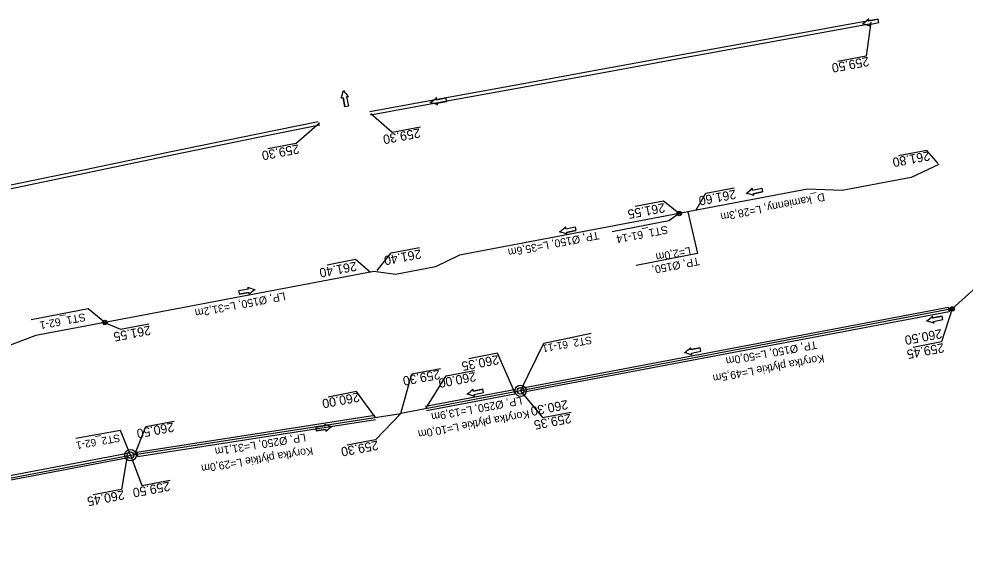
# Model space of a CAD drawing. Extents: x -1 to 65640748, y -22 to 5530284.
# Drawn here: x 6557044.8 to 6557152.5, y 5528580.5 to 5528641.5 of the extents above; entities that cross this region are included whole.
import ezdxf

# ---------------------------------------------------------------- set-up
doc = ezdxf.new("R2010")
doc.units = 0
for name, color, linetype in [('TOR_PROF-studnie i osadniki', 7, 'Continuous'), ('TOR_PS_ODW-drenaze', 7, 'Continuous'), ('TOR_PS_ODW-drenokolektory', 7, 'Continuous'), ('TOR_PS_ODW-studnie PEHD', 7, 'Continuous'), ('TOR_PS_OPIS_O-opisy rurociagow', 7, 'Continuous'), ('TOR_PS_OPIS_O-opisy studni', 7, 'Continuous'), ('TOR_PS_OPIS_T-INFO', 7, 'Continuous'), ('TOR_PS_T-rowy otwarte umocnione', 7, 'Continuous')]:
    doc.layers.add(name, color=color, linetype=linetype)

msp = doc.modelspace()

# ---------------------------------------------------------------- linework, layer by layer
at = {"layer": 'TOR_PROF-studnie i osadniki'}
for centre, radius in [((6557119.99, 5528619.34), 0.25), ((6557119.99, 5528619.34), 0.125), ((6557151.06, 5528608.48), 0.25), ((6557151.06, 5528608.48), 0.25), ((6557151.06, 5528608.48), 0.125), ((6557151.06, 5528608.48), 0.125), ((6557054.6, 5528606.95), 0.25), ((6557054.6, 5528606.95), 0.125), ((6557101.93, 5528599.17), 0.65), ((6557101.93, 5528599.17), 0.375), ((6557057.52, 5528591.83), 0.65), ((6557057.52, 5528591.83), 0.375)]:
    msp.add_circle(centre, radius, dxfattribs=at)
at = {"layer": 'TOR_PS_ODW-drenaze'}
for points in [[(6557149.52, 5528624.94), (6557146.39, 5528623.43), (6557138.55, 5528621.95), (6557134.58, 5528622.11), (6557121.96, 5528619.72)], [(6557121.96, 5528619.72), (6557119.99, 5528619.34)], [(6557119.99, 5528619.34), (6557094.96, 5528614.6), (6557092.25, 5528613.29), (6557087.68, 5528612.42), (6557085.22, 5528612.75)], [(6557151.06, 5528608.48), (6557101.93, 5528599.17)], [(6557054.6, 5528606.95), (6557046.73, 5528605.45), (6557043.51, 5528604.23), (6557029.81, 5528601.64), (6557026.15, 5528601.56)], [(6556998.57, 5528580.65), (6557057.52, 5528591.83)]]:
    msp.add_lwpolyline(points, dxfattribs=at)
at = {"layer": 'TOR_PS_ODW-drenokolektory'}
for points in [[(6557085.22, 5528612.75), (6557054.6, 5528606.95)], [(6557101.93, 5528599.17), (6557088.28, 5528596.59)], [(6557057.52, 5528591.83), (6557088.28, 5528596.59)]]:
    msp.add_lwpolyline(points, dxfattribs=at)
at = {"layer": 'TOR_PS_ODW-studnie PEHD'}
for centre, radius in [((6557119.99, 5528619.34), 0.25), ((6557119.99, 5528619.34), 0.112), ((6557054.6, 5528606.95), 0.25), ((6557054.6, 5528606.95), 0.112)]:
    msp.add_circle(centre, radius, dxfattribs=at)
at = {"layer": 'TOR_PS_OPIS_O-opisy rurociagow'}
for p, q in [((6557142.63, 5528641.46), (6557141.56, 5528641.27)), ((6557141.56, 5528641.27), (6557142.63, 5528641.46)), ((6557142.7, 5528641.07), (6557142.63, 5528641.46)), ((6557142.7, 5528641.07), (6557142.63, 5528641.46)), ((6557141.63, 5528640.87), (6557142.7, 5528641.07)), ((6557141.63, 5528640.87), (6557142.7, 5528641.07)), ((6557081.94, 5528631.49), (6557081.72, 5528632.56)), ((6557081.72, 5528632.56), (6557081.94, 5528631.49)), ((6557082.11, 5528632.64), (6557082.33, 5528631.57)), ((6557082.11, 5528632.64), (6557082.33, 5528631.57)), ((6557093.44, 5528632.5), (6557092.37, 5528632.3)), ((6557092.37, 5528632.3), (6557093.44, 5528632.5)), ((6557093.51, 5528632.11), (6557093.44, 5528632.5)), ((6557093.51, 5528632.11), (6557093.44, 5528632.5)), ((6557082.33, 5528631.57), (6557081.94, 5528631.49)), ((6557082.33, 5528631.57), (6557081.94, 5528631.49)), ((6557092.44, 5528631.91), (6557093.51, 5528632.11)), ((6557092.44, 5528631.91), (6557093.51, 5528632.11)), ((6557128.33, 5528621.99), (6557129.4, 5528622.21)), ((6557128.33, 5528621.99), (6557129.4, 5528622.21)), ((6557129.48, 5528621.81), (6557128.41, 5528621.59)), ((6557128.41, 5528621.59), (6557129.48, 5528621.81)), ((6557129.4, 5528622.21), (6557129.48, 5528621.81)), ((6557129.4, 5528622.21), (6557129.48, 5528621.81)), ((6557107.07, 5528617.59), (6557108.14, 5528617.81)), ((6557107.07, 5528617.59), (6557108.14, 5528617.81)), ((6557108.22, 5528617.42), (6557107.15, 5528617.2)), ((6557107.15, 5528617.2), (6557108.22, 5528617.42)), ((6557108.14, 5528617.81), (6557108.22, 5528617.42)), ((6557108.14, 5528617.81), (6557108.22, 5528617.42)), ((6557070.92, 5528610.74), (6557069.84, 5528610.55)), ((6557070.92, 5528610.74), (6557069.84, 5528610.55)), ((6557069.84, 5528610.55), (6557069.91, 5528610.16)), ((6557069.84, 5528610.55), (6557069.91, 5528610.16)), ((6557069.91, 5528610.16), (6557070.98, 5528610.35)), ((6557070.98, 5528610.35), (6557069.91, 5528610.16)), ((6557149.92, 5528607.67), (6557148.85, 5528607.45)), ((6557148.85, 5528607.45), (6557149.92, 5528607.67)), ((6557148.93, 5528607.06), (6557150, 5528607.28)), ((6557148.93, 5528607.06), (6557150, 5528607.28)), ((6557150, 5528607.28), (6557149.92, 5528607.67)), ((6557150, 5528607.28), (6557149.92, 5528607.67)), ((6557122.36, 5528604.06), (6557121.29, 5528603.85)), ((6557121.29, 5528603.85), (6557122.36, 5528604.06)), ((6557121.37, 5528603.46), (6557122.44, 5528603.67)), ((6557121.37, 5528603.46), (6557122.44, 5528603.67)), ((6557122.44, 5528603.67), (6557122.36, 5528604.06)), ((6557122.44, 5528603.67), (6557122.36, 5528604.06)), ((6557097.62, 5528599.35), (6557096.55, 5528599.13)), ((6557096.55, 5528599.13), (6557097.62, 5528599.35)), ((6557097.7, 5528598.96), (6557097.62, 5528599.35)), ((6557097.7, 5528598.96), (6557097.62, 5528599.35)), ((6557096.63, 5528598.74), (6557097.7, 5528598.96)), ((6557096.63, 5528598.74), (6557097.7, 5528598.96)), ((6557079.69, 5528595.16), (6557078.61, 5528594.98)), ((6557079.69, 5528595.16), (6557078.61, 5528594.98)), ((6557078.61, 5528594.98), (6557078.67, 5528594.59)), ((6557078.61, 5528594.98), (6557078.67, 5528594.59)), ((6557078.67, 5528594.59), (6557079.75, 5528594.77)), ((6557079.75, 5528594.77), (6557078.67, 5528594.59))]:
    msp.add_line(p, q, dxfattribs=at)
for points in [[(6557141.53, 5528641.49), (6557141.53, 5528641.49)], [(6557141.68, 5528640.66), (6557141.68, 5528640.66)], [(6557081.5, 5528632.5), (6557081.5, 5528632.5)], [(6557082.33, 5528632.68), (6557082.33, 5528632.68)], [(6557092.34, 5528632.53), (6557092.34, 5528632.53)], [(6557092.49, 5528631.69), (6557092.49, 5528631.69)], [(6557128.3, 5528622.21), (6557128.3, 5528622.21)], [(6557128.47, 5528621.38), (6557128.47, 5528621.38)], [(6557107.04, 5528617.82), (6557107.04, 5528617.82)], [(6557107.21, 5528616.98), (6557107.21, 5528616.98)], [(6557070.87, 5528610.96), (6557070.87, 5528610.96)], [(6557071.01, 5528610.12), (6557071.01, 5528610.12)], [(6557148.82, 5528607.67), (6557148.82, 5528607.67)], [(6557148.99, 5528606.84), (6557148.99, 5528606.84)], [(6557121.26, 5528604.07), (6557121.26, 5528604.07)], [(6557121.43, 5528603.24), (6557121.43, 5528603.24)], [(6557096.51, 5528599.36), (6557096.51, 5528599.36)], [(6557096.68, 5528598.52), (6557096.68, 5528598.52)], [(6557079.64, 5528595.38), (6557079.64, 5528595.38)], [(6557079.78, 5528594.54), (6557079.78, 5528594.54)]]:
    msp.add_lwpolyline(points, dxfattribs=at)
for centre, radius, start, end in [((6557138.11, 5528645.03), 4.92, 303.6559, 314.0378), ((6557138.11, 5528645.03), 4.92, 303.6559, 314.0378), ((6557141.1, 5528641.32), 0.458, 353.462, 21.9232), ((6557141.1, 5528641.32), 0.458, 353.462, 21.9232), ((6557139.73, 5528636.14), 4.92, 66.6181, 76.9999), ((6557139.73, 5528636.14), 4.92, 66.6181, 76.9999), ((6557141.22, 5528640.67), 0.458, 358.7326, 27.1939), ((6557141.22, 5528640.67), 0.458, 358.7326, 27.1939), ((6557076.94, 5528634.35), 4.92, 337.9125, 348.2944), ((6557076.94, 5528634.35), 4.92, 337.9125, 348.2944), ((6557081.5, 5528632.96), 0.458, 270.0271, 298.4883), ((6557081.5, 5528632.96), 0.458, 270.0271, 298.4883), ((6557085.79, 5528636.17), 4.92, 214.9504, 225.3323), ((6557085.79, 5528636.17), 4.92, 214.9504, 225.3323), ((6557082.15, 5528633.1), 0.458, 264.7564, 293.2177), ((6557082.15, 5528633.1), 0.458, 264.7564, 293.2177), ((6557088.92, 5528636.06), 4.92, 303.657, 314.0388), ((6557088.92, 5528636.06), 4.92, 303.657, 314.0388), ((6557091.91, 5528632.36), 0.458, 353.463, 21.9242), ((6557091.91, 5528632.36), 0.458, 353.463, 21.9242), ((6557090.54, 5528627.18), 4.92, 66.6191, 77.0009), ((6557090.54, 5528627.18), 4.92, 66.6191, 77.0009), ((6557092.03, 5528631.7), 0.458, 358.7336, 27.1949), ((6557092.03, 5528631.7), 0.458, 358.7336, 27.1949), ((6557124.8, 5528625.67), 4.92, 304.9397, 315.3215), ((6557124.8, 5528625.67), 4.92, 304.9397, 315.3215), ((6557127.88, 5528622.03), 0.458, 354.7457, 23.207), ((6557127.88, 5528622.03), 0.458, 354.7457, 23.207), ((6557126.62, 5528616.82), 4.92, 67.9018, 78.2836), ((6557126.62, 5528616.82), 4.92, 67.9018, 78.2836), ((6557128.01, 5528621.38), 0.458, 0.0164, 28.4776), ((6557128.01, 5528621.38), 0.458, 0.0164, 28.4776), ((6557103.54, 5528621.28), 4.92, 304.9397, 315.3215), ((6557103.54, 5528621.28), 4.92, 304.9397, 315.3215), ((6557106.62, 5528617.64), 0.458, 354.7457, 23.207), ((6557106.62, 5528617.64), 0.458, 354.7457, 23.207), ((6557105.36, 5528612.43), 4.92, 67.9018, 78.2836), ((6557105.36, 5528612.43), 4.92, 67.9018, 78.2836), ((6557106.75, 5528616.98), 0.458, 0.0164, 28.4776), ((6557106.75, 5528616.98), 0.458, 0.0164, 28.4776), ((6557072.86, 5528615.46), 4.92, 246.1449, 256.5268), ((6557071.32, 5528610.95), 0.458, 178.2595, 206.7208), ((6557072.86, 5528615.46), 4.92, 246.1449, 256.5268), ((6557071.32, 5528610.95), 0.458, 178.2595, 206.7208), ((6557071.44, 5528610.29), 0.458, 172.9889, 201.4501), ((6557071.44, 5528610.29), 0.458, 172.9889, 201.4501), ((6557074.4, 5528606.56), 4.92, 123.1828, 133.5647), ((6557074.4, 5528606.56), 4.92, 123.1828, 133.5647), ((6557145.33, 5528611.14), 4.92, 304.7998, 315.1816), ((6557145.33, 5528611.14), 4.92, 304.7998, 315.1816), ((6557147.13, 5528602.29), 4.92, 67.7619, 78.1437), ((6557147.13, 5528602.29), 4.92, 67.7619, 78.1437), ((6557148.4, 5528607.49), 0.458, 354.6058, 23.067), ((6557148.4, 5528607.49), 0.458, 354.6058, 23.067), ((6557148.53, 5528606.84), 0.458, 359.8764, 28.3377), ((6557148.53, 5528606.84), 0.458, 359.8764, 28.3377), ((6557117.77, 5528607.54), 4.92, 304.7998, 315.1816), ((6557117.77, 5528607.54), 4.92, 304.7998, 315.1816), ((6557119.57, 5528598.68), 4.92, 67.7619, 78.1437), ((6557119.57, 5528598.68), 4.92, 67.7619, 78.1437), ((6557120.84, 5528603.89), 0.458, 354.6058, 23.067), ((6557120.84, 5528603.89), 0.458, 354.6058, 23.067), ((6557120.97, 5528603.24), 0.458, 359.8764, 28.3377), ((6557120.97, 5528603.24), 0.458, 359.8764, 28.3377), ((6557093.02, 5528602.82), 4.92, 304.7941, 315.176), ((6557093.02, 5528602.82), 4.92, 304.7941, 315.176), ((6557096.09, 5528599.18), 0.458, 354.6002, 23.0614), ((6557096.09, 5528599.18), 0.458, 354.6002, 23.0614), ((6557094.82, 5528593.97), 4.92, 67.7563, 78.1381), ((6557094.82, 5528593.97), 4.92, 67.7563, 78.1381), ((6557096.22, 5528598.52), 0.458, 359.8708, 28.3321), ((6557096.22, 5528598.52), 0.458, 359.8708, 28.3321), ((6557081.66, 5528599.87), 4.92, 245.7393, 256.1211), ((6557080.1, 5528595.36), 0.458, 177.8538, 206.3151), ((6557081.66, 5528599.87), 4.92, 245.7393, 256.1211), ((6557080.1, 5528595.36), 0.458, 177.8538, 206.3151), ((6557083.14, 5528590.96), 4.92, 122.7772, 133.159), ((6557083.14, 5528590.96), 4.92, 122.7772, 133.159), ((6557080.21, 5528594.71), 0.458, 172.5832, 201.0444), ((6557080.21, 5528594.71), 0.458, 172.5832, 201.0444)]:
    msp.add_arc(centre, radius, start, end, dxfattribs=at)
at = {"layer": 'TOR_PS_OPIS_T-INFO'}
for points in [[(6557141.79, 5528641.11), (6557141.26, 5528637.27), (6557138.03, 5528636.65)], [(6557084.87, 5528630.74), (6557087.31, 5528628.6), (6557090.54, 5528629.2)], [(6557079.03, 5528629.62), (6557076.39, 5528627.31), (6557073.15, 5528626.69)], [(6557149.48, 5528625.02), (6557148.19, 5528626.53), (6557144.96, 5528625.9)], [(6557121.88, 5528619.7), (6557123.02, 5528621.67), (6557126.25, 5528622.28)], [(6557119.99, 5528619.34), (6557118.21, 5528620.76), (6557114.98, 5528620.14)], [(6557119.99, 5528619.34), (6557118.81, 5528618.51), (6557112.34, 5528617.26)], [(6557120.97, 5528619.53), (6557122.05, 5528614.81), (6557115.07, 5528613.44)], [(6557085.59, 5528612.85), (6557087.19, 5528614.87), (6557090.42, 5528615.47)], [(6557084.83, 5528612.63), (6557083.13, 5528614.1), (6557079.9, 5528613.47)], [(6557151.06, 5528608.48), (6557154.07, 5528611.18), (6557159.68, 5528612.23)], [(6557054.6, 5528606.95), (6557052.7, 5528608.5), (6557046.23, 5528607.25)], [(6557151.06, 5528608.48), (6557149.84, 5528604.72), (6557146.61, 5528604.1)], [(6557054.58, 5528606.94), (6557056.39, 5528606.19), (6557059.62, 5528606.79)], [(6557101.93, 5528599.17), (6557104.56, 5528604.59), (6557109.95, 5528605.74)], [(6557101.22, 5528599.06), (6557099.29, 5528603.43), (6557096.05, 5528602.81)], [(6557088.28, 5528596.59), (6557089.56, 5528601.11), (6557092.8, 5528601.71)], [(6557091.13, 5528597.15), (6557093.44, 5528600.88), (6557096.67, 5528601.48)], [(6557101.93, 5528599.17), (6557104.44, 5528596.11), (6557107.68, 5528596.72)], [(6557085.41, 5528596.12), (6557083.26, 5528599.07), (6557080.03, 5528598.44)], [(6557088.28, 5528596.59), (6557085.4, 5528593.59), (6557082.17, 5528592.97)], [(6557058.02, 5528591.91), (6557059.27, 5528595.11), (6557062.5, 5528595.72)], [(6557057.52, 5528591.83), (6557056.39, 5528594.66), (6557051.3, 5528593.73)], [(6557057.13, 5528591.76), (6557056.49, 5528587.94), (6557053.26, 5528587.31)], [(6557057.51, 5528591.83), (6557058.81, 5528588.38), (6557062.05, 5528588.98)]]:
    msp.add_lwpolyline(points, dxfattribs=at)
at = {"layer": 'TOR_PS_T-rowy otwarte umocnione'}
for p, q in [((6557150.64, 5528608.66), (6557102.19, 5528599.48)), ((6557101.18, 5528599.28), (6557091.12, 5528597.38)), ((6557058.24, 5528592.19), (6557085.34, 5528596.38)), ((6557057.17, 5528592.02), (6556998.83, 5528580.96))]:
    msp.add_line(p, q, dxfattribs=at)
for points in [[(6557141.75, 5528641.31), (6557130.96, 5528639.34), (6557121.12, 5528637.55), (6557111.28, 5528635.76), (6557101.44, 5528633.97), (6557091.6, 5528632.17), (6557084.77, 5528630.91)], [(6557141.82, 5528640.92), (6557131.03, 5528638.95), (6557121.19, 5528637.16), (6557111.36, 5528635.37), (6557101.52, 5528633.57), (6557091.68, 5528631.78), (6557084.84, 5528630.52)], [(6557078.89, 5528629.78), (6557071.97, 5528628.39), (6557062.17, 5528626.36), (6557052.38, 5528624.32), (6557042.59, 5528622.29), (6557032.8, 5528620.25), (6557023, 5528618.21), (6557013.21, 5528616.18), (6557003.42, 5528614.14), (6556993.63, 5528612.11), (6556987.85, 5528610.91)], [(6557079.07, 5528629.41), (6557072.04, 5528628), (6557062.25, 5528625.97), (6557052.46, 5528623.93), (6557042.66, 5528621.89), (6557032.87, 5528619.86), (6557023.08, 5528617.82), (6557013.29, 5528615.79), (6557003.49, 5528613.75), (6556993.7, 5528611.71), (6556987.94, 5528610.51), (6556987.85, 5528610.91)], [(6557150.64, 5528608.66), (6557150.73, 5528608.17), (6557102.28, 5528598.99)], [(6557101.18, 5528599.28), (6557101.27, 5528598.79), (6557091.22, 5528596.89)], [(6557058.24, 5528592.19), (6557058.31, 5528591.7), (6557085.41, 5528595.89)], [(6557057.26, 5528591.52), (6556998.92, 5528580.47), (6556998.83, 5528580.96)]]:
    msp.add_lwpolyline(points, dxfattribs=at)

# ---------------------------------------------------------------- texts
at = {"layer": 'TOR_PS_OPIS_O-opisy rurociagow'}
for s, rotation, p in [('D_kamienny, L=28,3m', 191.128, (6557136.47, 5528621.68)), ('TP, Ø150, L=35,6m', 190.9157, (6557110.77, 5528617.31)), ('L=2,0m', 190.9157, (6557121.22, 5528615.55)), ('TP, Ø150, ', 190.9157, (6557122.2, 5528614.37)), ('LP, Ø150, L=31,2m', 190.9157, (6557075.07, 5528610.39)), ('TP, Ø150, L=50,0m', 190.3854, (6557135.59, 5528604.85)), ('Korytka płytkie L=49,5m', 190.3854, (6557136.41, 5528603.31)), ('LP, Ø250, L=13,9m', 190.3854, (6557102, 5528598.49)), ('Korytka płytkie L=10,0m', 190.3854, (6557102.85, 5528596.95)), ('LP, Ø250, L=31,1m', 189.0561, (6557077.41, 5528594.31)), ('Korytka płytkie L=29,0m', 189.0561, (6557078.23, 5528592.76))]:
    msp.add_text(s, height=0.9, rotation=rotation, dxfattribs=at).set_placement(p)
at = {"layer": 'TOR_PS_OPIS_O-opisy studni'}
for s, height, rotation, p in [('ST1_61-14', 0.9, 191.0808, (6557118.61, 5528617.96)), ('ST1_62-1', 0.9, 190.7349, (6557052.32, 5528608.01)), ('ST2_61-11', 0.862, 190.2953, (6557109.95, 5528605.38)), ('ST2_62-1', 0.862, 190.1109, (6557056.25, 5528594.23))]:
    msp.add_text(s, height=height, rotation=rotation, dxfattribs=at).set_placement(p)
at = {"layer": 'TOR_PS_OPIS_T-INFO'}
for s, rotation, p in [('259.50', 190.7159, (6557141.49, 5528637.19)), ('259.30', 190.7506, (6557090.41, 5528629.05)), ('259.30', 190.7159, (6557076.62, 5528627.22)), ('261.80', 190.7159, (6557148.42, 5528626.44)), ('261.60', 190.7506, (6557126.35, 5528622.07)), ('261.55', 190.7159, (6557118.26, 5528620.54)), ('261.40', 190.7506, (6557090.52, 5528615.27)), ('261.40', 190.7159, (6557083.17, 5528613.87)), ('261.55', 190.7506, (6557059.73, 5528606.59)), ('260.50', 190.7159, (6557149.8, 5528606.2)), ('259.45', 190.7159, (6557150.04, 5528604.6)), ('260.35', 190.7159, (6557099.35, 5528603.24)), ('259.30', 190.7506, (6557092.67, 5528601.57)), ('260.00', 190.7506, (6557096.74, 5528601.31)), ('260.00', 190.7159, (6557083.49, 5528598.98)), ('260.30', 190.7506, (6557107.22, 5528598.13)), ('259.35', 190.7506, (6557107.59, 5528596.56)), ('260.50', 190.7506, (6557062.37, 5528595.57)), ('259.30', 190.7159, (6557085.63, 5528593.5)), ('259.50', 190.7506, (6557061.92, 5528588.84)), ('260.45', 190.7159, (6557056.73, 5528587.85))]:
    msp.add_text(s, height=1.05, rotation=rotation, dxfattribs=at).set_placement(p)

doc.saveas('drawing.dxf')
